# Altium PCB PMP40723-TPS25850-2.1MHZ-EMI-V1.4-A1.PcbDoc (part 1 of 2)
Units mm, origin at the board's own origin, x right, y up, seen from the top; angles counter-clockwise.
Board outline 50 x 35 mm, 4 copper layers (Top Layer, Signal Layer 1, Signal Layer 2, Bottom Layer), stack 1.647 mm thick; 79 components, 26 nets, 228 pads, 232 vias.
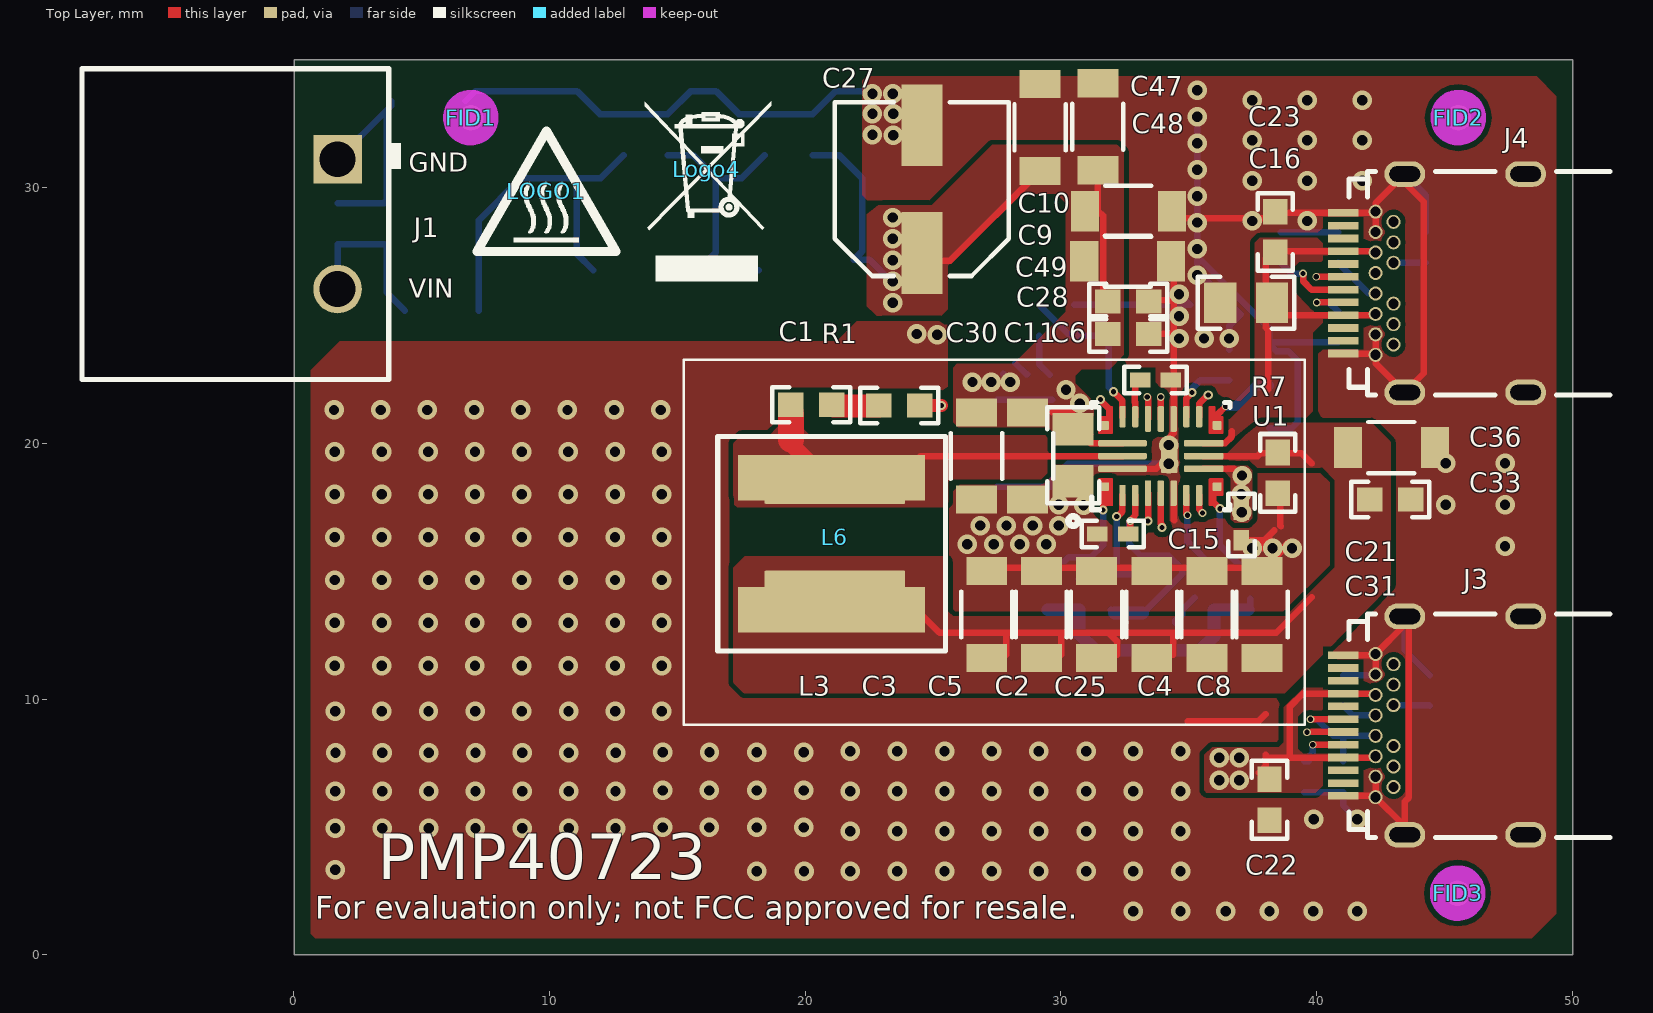
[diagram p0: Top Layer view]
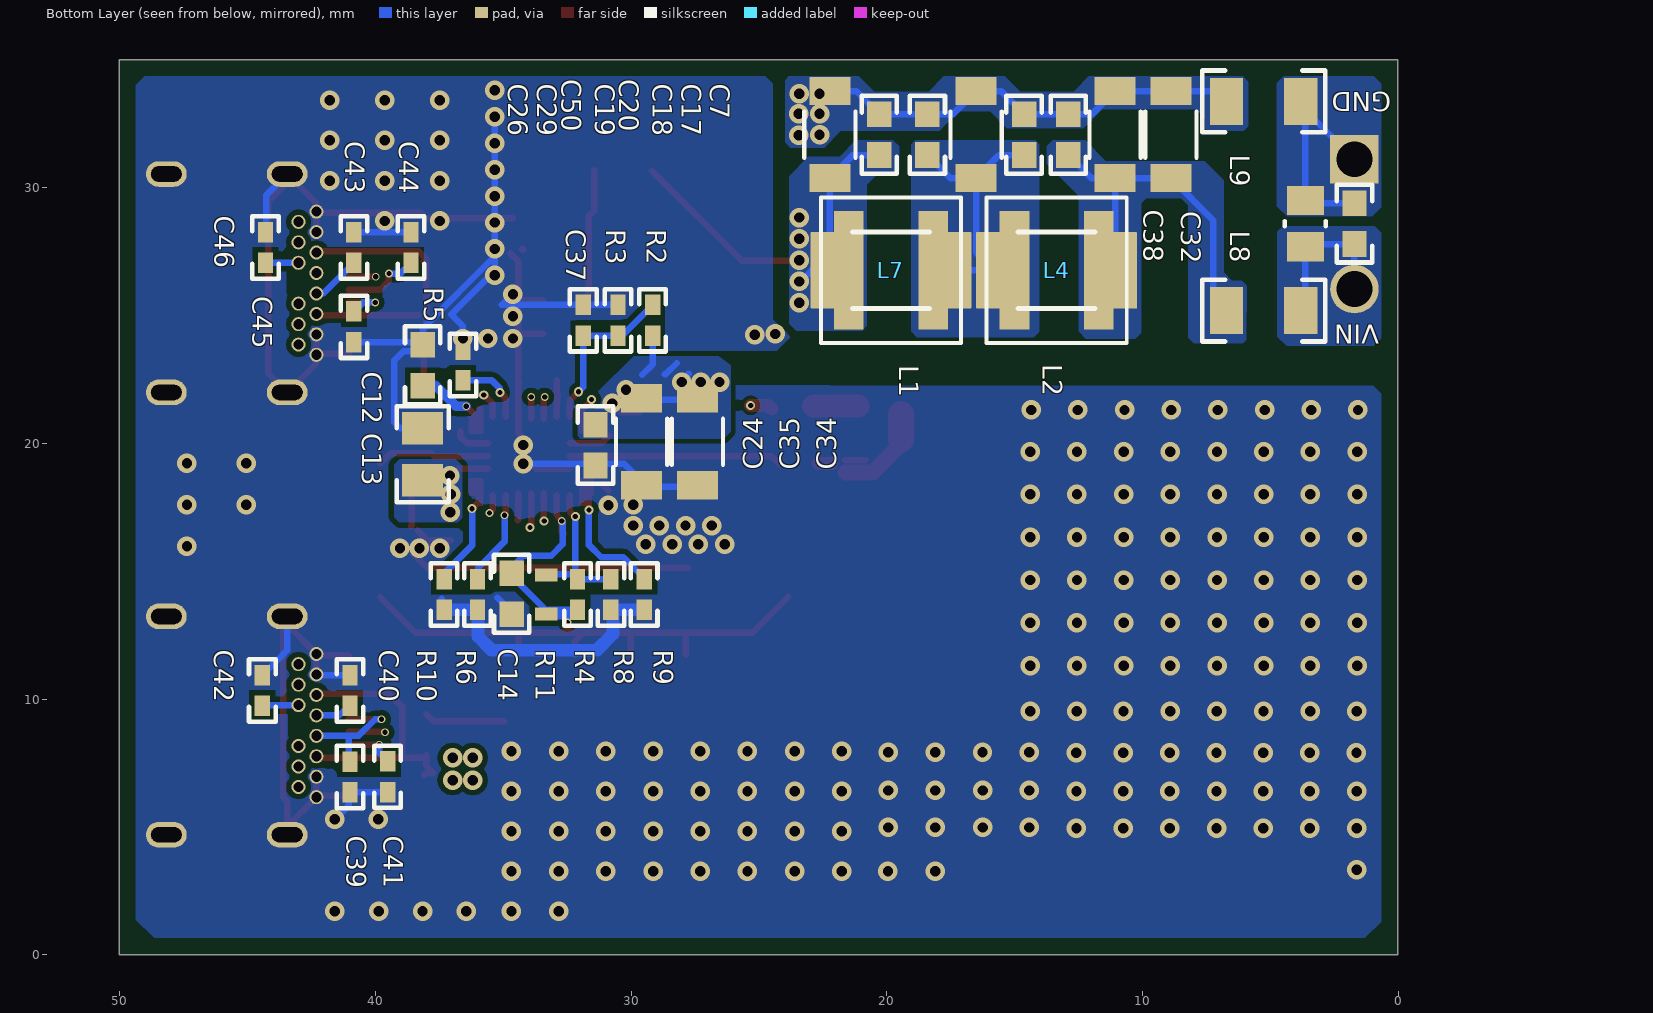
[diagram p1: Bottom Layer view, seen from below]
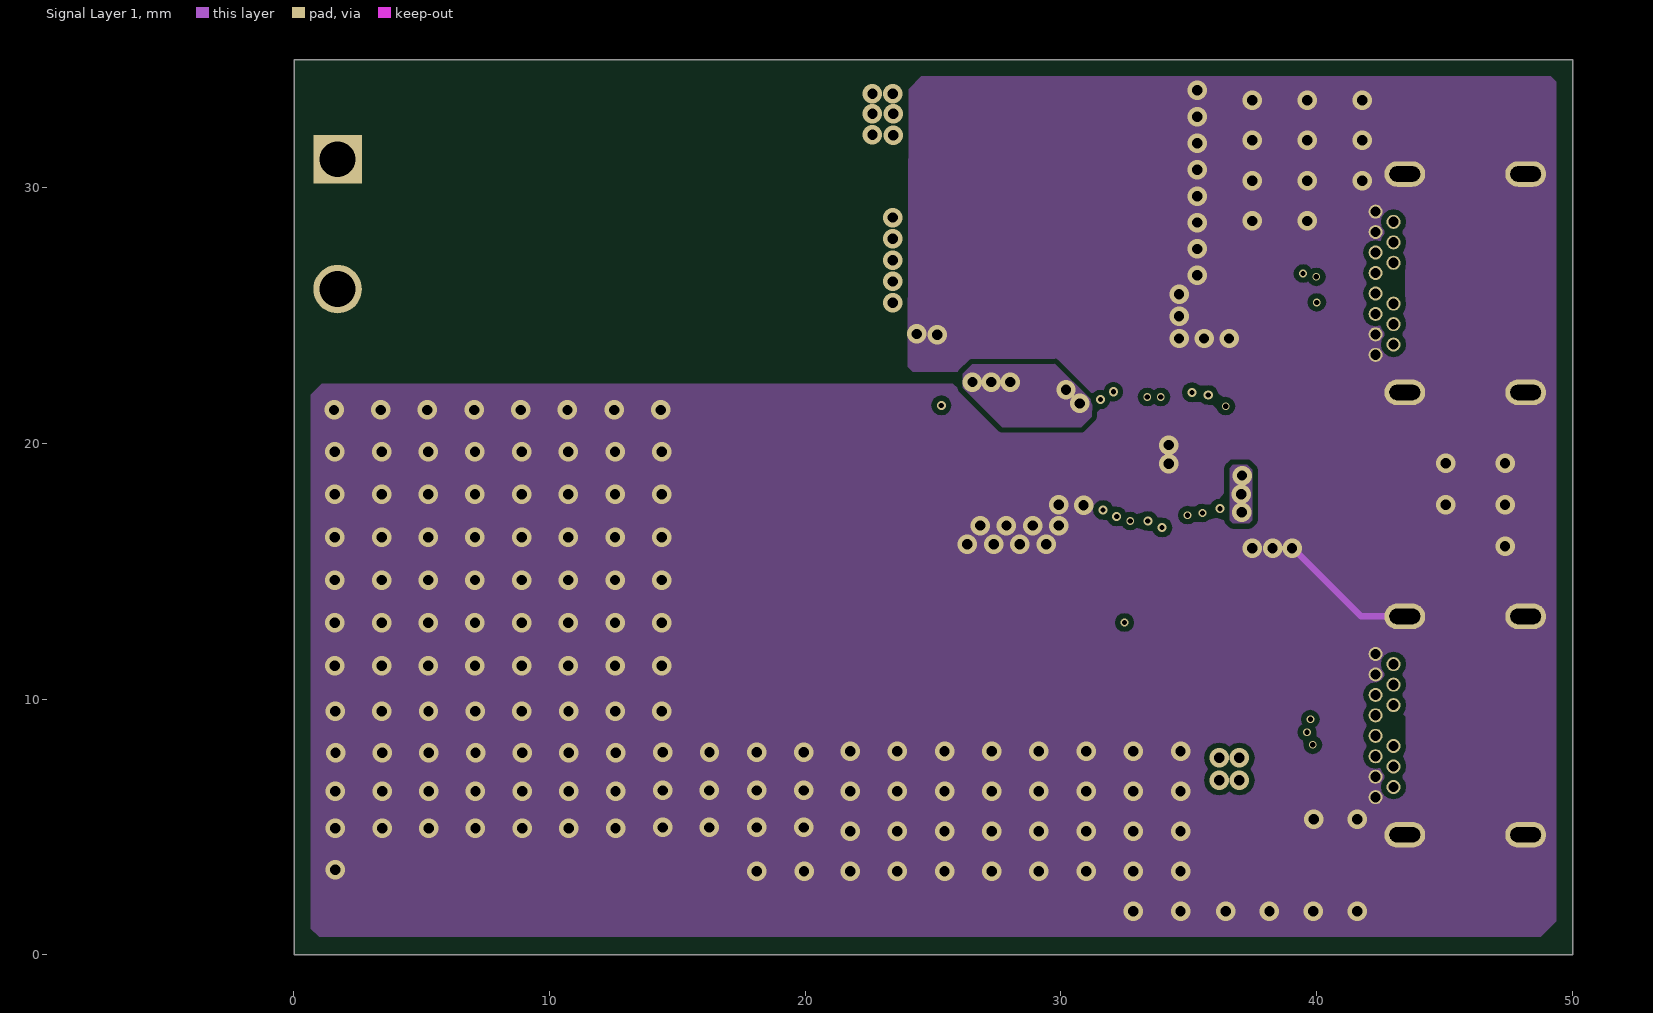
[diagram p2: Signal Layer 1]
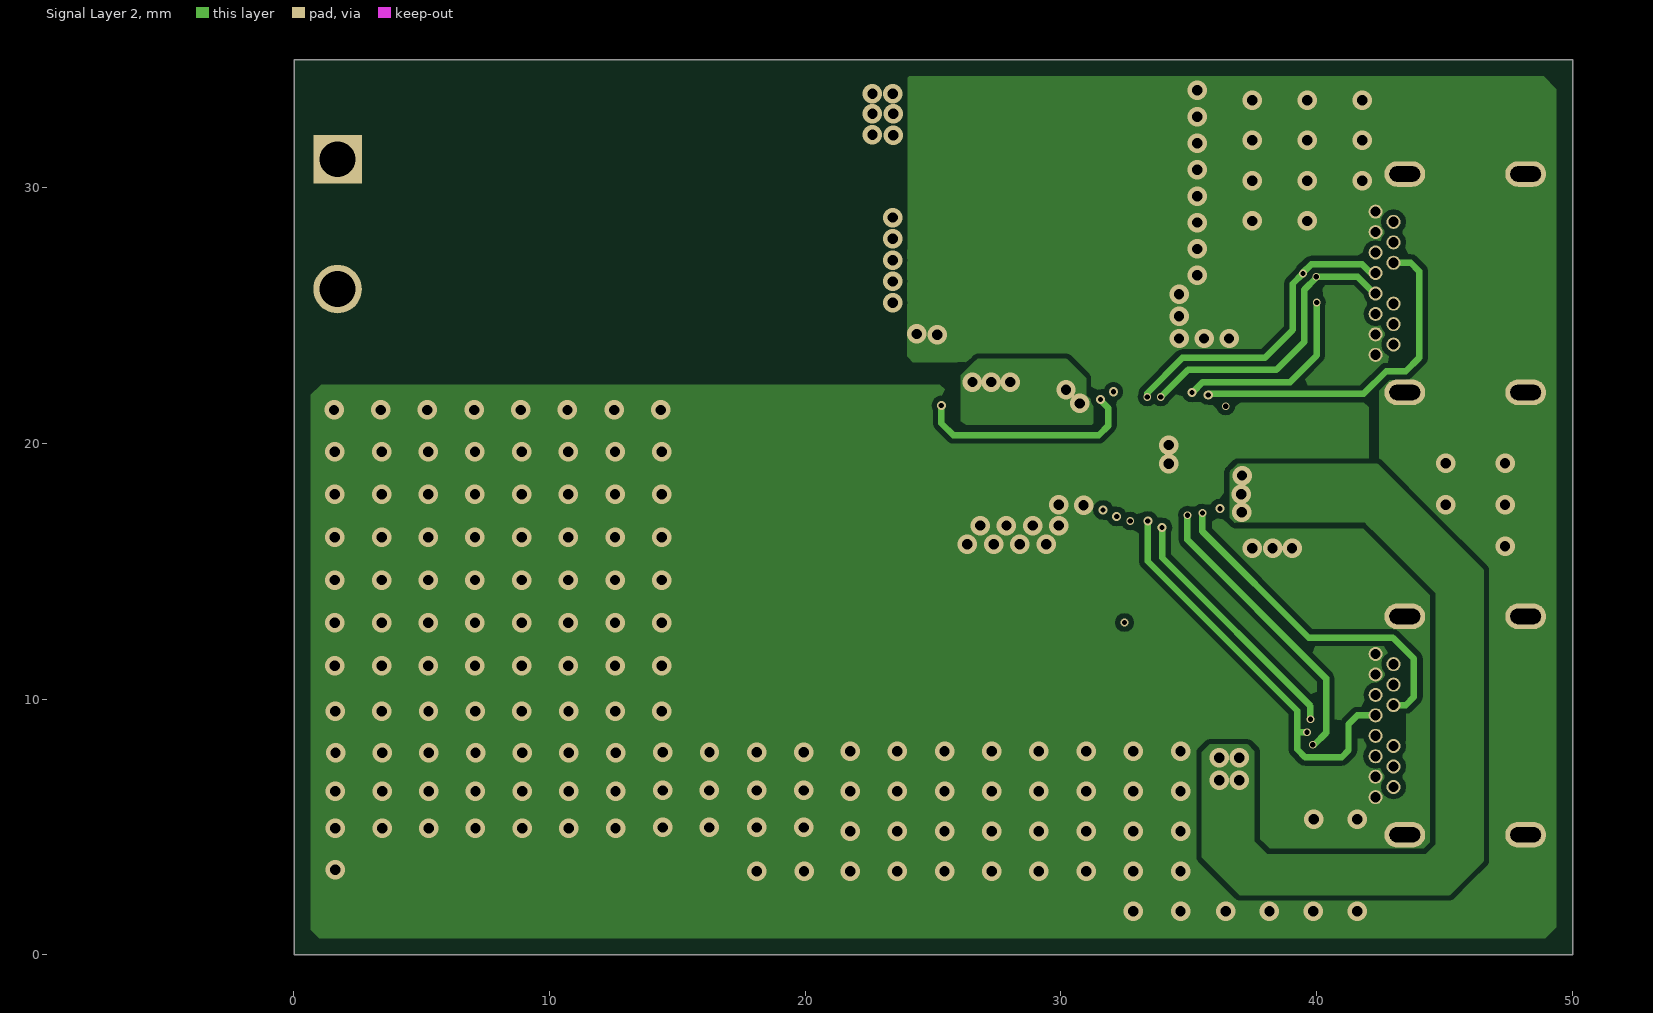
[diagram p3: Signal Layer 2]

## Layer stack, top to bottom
Top Solder: solder mask 0.0102, Solder Resist, Dk 3.5
Top Layer: signal copper 0.0356
Signal Layer 1: signal copper 0.036
Signal Layer 2: signal copper 0.036
Dielectric1: core 1.5037, FR-4, Dk 4.8
Bottom Layer: signal copper 0.0356
Bottom Solder: solder mask 0.0102, Solder Resist, Dk 3.5

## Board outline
0.021,0 0.021,35 50.021,35 50.021,0

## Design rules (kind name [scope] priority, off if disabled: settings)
AcuteAngle [All] p1: minimum=4.50000000000000E+0001 checktracksonly=FALSE
AssemblyTestPointUsage [All] p1: valid=2
BoardOutlineClearance BoardOutlineClearance_MountingHoles [OnCopper and InComponentClass('Mounting Holes')] p1: gap=0.635 ignorepadtopadclearanceinfootprint=FALSE
BoardOutlineClearance BoardOutlineClearance_Poly [OnCopper and IsPoly] p2: gap=0.635 ignorepadtopadclearanceinfootprint=FALSE
BoardOutlineClearance [OnCopper and Not InComponentClass('Logo') and not InComponentClass('FiducialMark') and not InRegion(1000,500,4000,800) and not InPoly] p3: gap=0.61 ignorepadtopadclearanceinfootprint=FALSE
Clearance Clearance_1 [All] p1: gap=0.203 ignorepadtopadclearanceinfootprint=FALSE
Clearance Clearance_Keepouts [((IsTrack Or IsArc) And Not InPoly) And IsFree and IsKeepOut vs ((IsTrack Or IsArc) And Not InPoly) And IsFree and IsKeepOut] p2: gap=0 ignorepadtopadclearanceinfootprint=FALSE
Clearance Clearance_Poly [InPolygon] p3: gap=0.254 ignorepadtopadclearanceinfootprint=TRUE
Clearance Clearance_FiducialMark [IsKeepOut and InComponentClass('FiducialMark') vs IsPad and InComponentClass('FiducialMark')] p4: gap=0 ignorepadtopadclearanceinfootprint=FALSE
Clearance [All] p5: gap=0.152 ignorepadtopadclearanceinfootprint=TRUE
ComponentClearance ComponentClearance_MountingHoles_FiducialMarks [InComponentClass('Mounting Holes') vs InComponentClass('FiducialMark')] p1: gap=1.27 collisioncheckmode=3 verticalgap=0.254 showdistances=FALSE
ComponentClearance ComponentClearance_Shunt [InComponentClass('Header') vs InComponentClass('Shunt')] p2: gap=0 collisioncheckmode=3 verticalgap=0 showdistances=FALSE
ComponentClearance ComponentClearance_Logo [InComponentClass('Logo')] p3: gap=1.27 collisioncheckmode=3 verticalgap=0.254 showdistances=FALSE
ComponentClearance ComponentClearance_ScrewToNut [(HasFootprint('NY PMS 440 0025 PH')) vs (HasFootprint('Keystone_1902C'))] p4: gap=0.127 collisioncheckmode=3 verticalgap=0.254 showdistances=FALSE
ComponentClearance ComponentClearance_MountingHoles [InComponentClass('Mounting Holes')] p5: gap=6.35 collisioncheckmode=3 verticalgap=2540 showdistances=FALSE
ComponentClearance ComponentClearance_SmallPassives [HasFootprint('0201*') or HasFootprint('0402*') or HasFootprint('0508') or HasFootprint('0603*') or HasFootprint('0612') or HasFootprint('0805*') or HasFootprint('0815*') or HasFootprint('0830*') or HasFootprint('1206*') or HasFootprint('1210*') or HasFootprint('1808*') or HasFootprint('1812*') or HasFootprint('1825*') or HasFootprint('2010*') or HasFootprint('2220*') or HasFootprint('2225*') or HasFootprint('2512*') or HasFootprint('2728*') or HasFootprint('3518*') vs HasFootprint('0201*') or HasFootprint('0402*') or HasFootprint('0508') or HasFootprint('0603*') or HasFootprint('0612') or HasFootprint('0805*') or HasFootprint('0815*') or HasFootprint('0830*') or HasFootprint('1206*') or HasFootprint('1210*') or HasFootprint('1808*') or HasFootprint('1812*') or HasFootprint('1825*') or HasFootprint('2010*') or HasFootprint('2220*') or HasFootprint('2225*') or HasFootprint('2512*') or HasFootprint('2728*') or HasFootprint('3518*')] p6: gap=0.254 collisioncheckmode=3 verticalgap=0.254 showdistances=FALSE
ComponentClearance ComponentClearance_THtoSMT [IsThruComponent vs IsSMTComponent] p7: gap=1.016 collisioncheckmode=3 verticalgap=0.762 showdistances=FALSE
ComponentClearance ComponentClearance_THtoTH [IsThruComponent vs IsThruComponent] p8: gap=0.762 collisioncheckmode=3 verticalgap=0.762 showdistances=FALSE
ComponentClearance [All] p9: gap=0.762 collisioncheckmode=3 verticalgap=0.254 showdistances=FALSE
DiffPairsRouting [All] p1: maxlimit=2.54 minlimit=0.203 mostfreqgap=0.254 toplayer_minwidth=0.254 toplayer_maxwidth=0.381 toplayer_prefwidth=0.254 midlayer1_minwidth=0.254 midlayer1_maxwidth=0.381 midlayer1_prefwidth=0.254 midlayer2_minwidth=0.254 midlayer2_maxwidth=0.381 midlayer2_prefwidth=0.254 bottomlayer_minwidth=0.254 bottomlayer_maxwidth=0.381 bottomlayer_prefwidth=0.254 maxuncoupledlength=25.4
FabricationTestPointUsage TestPointUsage [All] p1: valid=2 allowmultiple=FALSE
FabricationTestpoint Testpoint [All] p1: side=3 testpointundercomponent=TRUE minsize=1.016 maxsize=2.54 preferedsize=1.524 minholesize=0 maxholesize=1.016 preferedholesize=0.813 testpointgrid=0.025 allowsidetop=TRUE allowsidebottom=TRUE usegrid=TRUE gridtolerance=0
FanoutControl Fanout_LCC [IsLCC] p1: bgadir=Out bgaviamode=Centered fanoutstyle=Auto fanoutdirection=Alternating viagrid=0.025 // Fanout_LCC (Default Rule)
FanoutControl Fanout_BGA [IsBGA] p2: bgadir=Out bgaviamode=Centered fanoutstyle=Auto fanoutdirection=Alternating viagrid=0.025 // Fanout_BGA (Default Rule)
FanoutControl Fanout_Default [All] p4: bgadir=Out bgaviamode=Centered fanoutstyle=Auto fanoutdirection=Alternating viagrid=0.025 // Fanout_Default (Default Rule)
FanoutControl Fanout_Small [(CompPinCount < 5)] p5: bgadir=Out bgaviamode=Centered fanoutstyle=Auto fanoutdirection=OutThenIn viagrid=0.025 // Fanout_Small (Default Rule)
HoleSize [All] p1: absolutevalues=TRUE maxlimit=6.375 minlimit=0.2 maxpercent=80.000 minpercent=20.000
HoleToHoleClearance [All] p1: gap=0.203 allowstackedmicrovias=TRUE
MinimumAnnularRing MinimumAnnularRing_ThermalPadVias [IsVia and InAnyComponent] p1: minimumring=0.076
MinimumAnnularRing [All] p2: minimumring=0.051
MinimumSolderMaskSliver MinimumSolderMaskSliver_Logo [InComponentClass('Logo') vs InComponentClass('Logo')] p1: minsoldermaskwidth=0.01
MinimumSolderMaskSliver [All] p2: minsoldermaskwidth=0.1
PlaneClearance [All] p1: clearance=0.254
PlaneConnect [All] p1: planeconnectstyle=Relief reliefexpansion=0.254 reliefentries=4 reliefconductorwidth=0.254 reliefairgap=0.254
PolygonConnect [All] p1: connectstyle=Direct reliefconductorwidth=0.254 reliefentries=4 polygonreliefangle="90 Angle" airgapwidth=0.254
RoutingVias ThermalPadVias [IsVia and InAnyComponent] p1: holewidth=0.2 width=0.5 viastyle="Through Hole" minholewidth=0.2 minwidth=0.5 maxholewidth=0.33 maxwidth=0.6
RoutingVias [All] p2: holewidth=0.406 width=0.762 viastyle="Through Hole" minholewidth=0.203 minwidth=0.305 maxholewidth=0.508 maxwidth=0.762
SilkToBoardRegionClearance [Not ((IsComment or IsDesignator) And (Hide <> 'False')) and not InRegion(1000,500,4000,800)] p1:
SilkToSilkClearance SilkToSilkClearance_Pb-FreeLogo [(HasFootprint('Pb-Free_Overlay_Medium') OR HasFootprint('Pb-Free_Overlay_Small')) vs (HasFootprint('Pb-Free_Overlay_Medium') OR HasFootprint('Pb-Free_Overlay_Small'))] p1: silktosilkclearance=0
SilkToSilkClearance [All] p2: silktosilkclearance=0.1
SilkToSolderMaskClearance SilkToComponentPadClearance [(IsPad or IsFill or IsRegion) and InAnycomponent] p1: minsilkscreentomaskgap=0.127 clearancetoexposedcopper=TRUE
SilkToSolderMaskClearance "Silk to Solder Mask Opening" [All] p2: minsilkscreentomaskgap=0.1 clearancetoexposedcopper=FALSE
SolderMaskExpansion [All] p1: expansion=0.05
UnRoutedNet [All] p1: checkbadconnections=TRUE
Width [All] p1: maxlimit=2.54 minlimit=0.152 preferedwidth=0.254 checkconnectedcopper=TRUE
12 further rules are at their usual default settings.

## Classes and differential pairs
component class PMP40723-TPS25850-2.1MHZ-EMI-V1.3-A1: C1 C2 C3 C4 C5 C6 C7 C8 C9 C10 C11 C12 C13 C14 C15 C16 C17 C18 C19 C20 C21 C22 C23 C24 C25 C26 C27 C28 C29 C30 C31 C32 C33 C34 C35 C36 C37 C38 C39 C40 C41 C42 C43 C44 C45 C46 C47 C48 C49 C50 C? J1 J3 J4 L1 L2 L3 L4 L6 L7 L8 L9 R1 R2 R3 R4 R5 R6 R7 R8 R9 R10 R? RT1 U1
component class PMP40723-TPS25850-2.1MHZ-EMI-V1.3-A0: FID1 FID2 FID3 LOGO1 Logo2 Logo3 Logo4
component class FiducialMark: FID1 FID2 FID3

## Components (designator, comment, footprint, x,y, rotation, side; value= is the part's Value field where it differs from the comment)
C1 "C0603C104K5RACAUTO" 0603 20.239,21.514 r0 top value=0.1uF
C2 "GRM31CR71A226ME15L" 1206_180 31.39,13.31 r90 top value=22uF
C3 "GRM31CR71A226ME15L" 1206_180 27.097,13.31 r90 top value=22uF
C4 "GRM31CR71A226ME15L" 1206_180 35.708,13.31 r90 top value=22uF
C5 "GRM31CR71A226ME15L" 1206_180 29.231,13.31 r90 top value=22uF
C6 "CL21B104MBCNNNC" 0805_HV 30.475,19.533 r270 top value=0.1uF
C7 "CGA5L1X7R1H106K160AC" 1206_190 8.885,32.08 r90 bottom value=10uF
C8 "GRM31CR71A226ME15L" 1206_180 37.867,13.31 r90 top value=22uF
C9 "GRT31CR61H106KE01L" 1206_180 32.609,27.127 r0 top value=10uF
C10 "GRT31CR61H106KE01L" 1206_180 32.634,29.083 r0 top value=10uF
C11 "GRT31CR61H106KE01L" 1206_180 28.697,19.509 r270 top value=10uF
C12 "885012106018" 0603 38.146,23.063 r90 bottom value=2.2uF
C13 "C2012X7R1A106M125AC" 0805_HV 38.147,19.584 r90 bottom value=10uF
C14 "885012106018" 0603 34.666,14.123 r270 bottom value=2.2uF
C15 "GRM155R71C104JA88D" 0402 32.025,16.459 r180 top value=0.1uF
C16 "C2012X7R1A106M125AC" 0805_HV 37.236,25.502 r180 top value=10uF
C17 "GCM31CR71H225KA55L" 1206_180 11.07,32.08 r90 bottom value=2.2uF
C18 "C0603C222K5RACTU" 0603 12.898,32.08 r90 bottom value=2200pF
C19 "GCM31CR71H225KA55L" 1206_180 16.505,32.08 r90 bottom value=2.2uF
C20 "C0603C222K5RACTU" 0603 14.626,32.08 r90 bottom value=2200pF
C21 "C0603C104K5RACAUTO" 0603 38.476,18.847 r270 top value=0.1uF
C22 "C0603C104K5RACAUTO" 0603 38.154,6.071 r270 top value=0.1uF
C23 "C0603C104K5RACAUTO" 0603 38.379,28.27 r90 top value=0.1uF
C24 "C0603C104K5RACAUTO" 0603 31.39,19.939 r270 bottom value=0.1uF
C25 "GRM31CR71A226ME15L" 1206_180 33.549,13.31 r90 top value=22uF
C26 "CGA5L3X7R1H475K160AE" 1206_190 22.22,32.08 r90 bottom value=4.7uF
C27 "EEE-FK1V101XP" SM_RADIAL_D8 24.557,29.947 r90 top value=100uF
C28 "GCM188R71H472KA37D" 0603 32.634,24.283 r0 top value=4700pF
C29 "GRM188R71H332KA01D" 0603 20.29,32.08 r90 bottom value=3300pF
C30 "GRT31CR61H106KE01L" 1206_180 26.691,19.507 r270 top value=10uF
C31 "GRM155R71C104JA88D" 0402 37.054,16.815 r270 top value=0.1uF
C32 "C0603C104K5RACAUTO" 0603 1.706,28.601 r90 bottom value=0.1uF
C33 "C0603X222K5RACTU" 0603 42.87,17.806 r0 top value=2200pF
C34 "GRT31CR61H106KE01L" 1206_180 27.402,20.066 r270 bottom value=10uF
C35 "GRT31CR61H106KE01L" 1206_180 29.586,20.066 r270 bottom value=10uF
C36 "GRM31CR71A226ME15L" 1206_180 42.921,19.838 r0 top value=22uF
C37 "C0402C104K4RACAUTO" 0402 31.866,24.816 r90 bottom value=0.1uF
C38 "CEU4J2X7R1H104K125AE" 0805_150 3.627,28.601 r90 bottom value=0.1uF
C39 "GRM155R71C104JA88D" 0402 40.991,6.96 r270 bottom value=0.1uF
C40 "GRM155R71C104JA88D" 0402 40.991,10.338 r90 bottom value=0.1uF
C41 "GRM155R71C104JA88D" 0402 39.518,6.967 r270 bottom value=0.1uF
C42 "GRM155R71C104JA88D" 0402 44.42,10.338 r90 bottom value=0.1uF
C43 "GRM155R71C104JA88D" 0402 40.838,27.661 r90 bottom value=0.1uF
C44 "GRM155R71C104JA88D" 0402 38.603,27.661 r90 bottom value=0.1uF
C45 "GRM155R71C104JA88D" 0402 40.838,24.562 r270 bottom value=0.1uF
C46 "GRM155R71C104JA88D" 0402 44.293,27.661 r90 bottom value=0.1uF
C47 "GRT31CR61H106KE01L" 1206_180 29.18,32.36 r90 top value=10uF
C48 "GRT31CR61H106KE01L" 1206_180 31.44,32.385 r90 top value=10uF
C49 "C0603C104K5RACAUTO" 0603 32.634,25.553 r0 top value=0.1uF
C50 "C0603C222K5RACTU" 0603 18.41,32.08 r90 bottom value=2200pF
FID1 "Fiducial" Fiducial10-20 6.92,32.741 r0 top
FID2 "Fiducial" Fiducial10-20 45.537,32.741 r0 top
FID3 "Fiducial" Fiducial10-20 45.512,2.413 r0 top
J1 "1757242" PHOENIX_1757242 -2.291,28.575 r270 top locked
J3 "632723300011" Wurth_632_723_300_011 51.624,8.967 r90 top locked (schematic designator J1)
J4 "632723300011" Wurth_632_723_300_011 51.624,26.267 r90 top locked
L1 "74279252" 1812_170_HighSpeed 19.833,26.772 r0 bottom value="880 ohm"
L2 "XAL5030-102MEB" XAL5030 13.356,26.772 r0 bottom value=1uH
L3 "XAL8080-102ME" XAL8080 21.026,16.078 r270 top value=4.7uH
L4 "NC" 1812_170_HighSpeed 13.356,26.772 r0 bottom value="880 ohm"
L6 "XAL6060-472MEB" XAL6060 21.153,16.332 r270 top value=4.7uH
L7 "XAL5030-102MEB" XAL5030 19.833,26.772 r0 bottom value=1uH
L8 "MPZ2012S300ATD25" 1206 5.256,25.197 r0 bottom value="110 ohm"
L9 "MPZ2012S300ATD25" 1206 5.256,33.376 r0 bottom value="110 ohm"
LOGO1 "CAUTION HOT SURFACE" IEC_HotSurface_Small 9.876,29.871 r0 top
Logo3 "FCC disclaimer" FCC_disclaimer -11.366,-5.562 r0 top
Logo4 "WEEE logo" WEEE_Minimum 16.15,30.723 r0 top
R1 "RMCF0603ZT0R00" 0603 23.668,21.489 r180 top value=0
R2 "CRCW040220K0JNED" 0402 29.154,24.816 r270 bottom value=20k
R3 "CRCW04025K10JNED" 0402 30.51,24.816 r270 bottom value=5.1k
R4 "ERJ-2GEJ393X" 0402 32.092,14.097 r270 bottom value=39k
R5 "CRCW04025K10JNED" 0402 36.571,23.063 r270 bottom value=5.1k
R6 "CRCW04025K10JNED" 0402 36.004,14.097 r90 bottom value=5.1k
R7 "CRCW04028K87FKED" 0402 33.701,22.479 r180 top value=8.87k
R8 "ERJ-2GEJ393X" 0402 30.788,14.097 r90 bottom value=39k
R9 "MCR01MZPJ000" 0402 29.485,14.097 r90 bottom value=0
R10 "MCR01MZPJ000" 0402 37.308,14.097 r90 bottom value=0
RT1 "NCP18WM474J03RB" 0603S 33.312,14.097 r270 bottom value=470k
U1 "TPS25850QRPQRQ1" RPQ0025A 33.904,19.507 r90 top locked

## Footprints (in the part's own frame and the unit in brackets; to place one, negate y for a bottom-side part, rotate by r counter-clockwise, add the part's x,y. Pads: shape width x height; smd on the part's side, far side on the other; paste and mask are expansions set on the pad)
0402 [mm] "0402 from SM-752 data"
  rect 0.8x0.6 smd: 1(-0.6,0) 2(0.6,0)
  silkscreen extent -1.22,-0.52 1.22,0.52, body extent -0.55,-0.3 0.55,0.3, height 0.6
0603 [mm] "0603 from SM-752 data"
  rect 1x0.95 smd: 1(-0.8,0) 2(0.8,0)
  silkscreen extent -1.52,-0.69 1.52,0.69, body extent -0.87,-0.47 0.87,0.47, height 1
0603S [mil]
  rect 20x35 smd: 1(-30,0) 2(30,0)
  body extent -34,-19 34,19, height 39
0805_150 [mm] "0805 / 1.5 mm height"
  rect 1.15x1.45 smd: 1(-0.9,0) 2(0.9,0)
  silkscreen extent -0.1,-0.8 0.1,0.8, body extent -1.1,-0.72 1.1,0.72, height 1.5
0805_HV [mil] "0805 with 30mil clearance between pads"
  rect 50x63 smd: 1(-40,0) 2(40,0)
  silkscreen extent -74,-40 74,40, body extent -43,-29 43,29, height 57
1206 [mm] "1206 from SM-752 data"
  rect 1.3x1.85 smd: 1(-1.45,0) 2(1.45,0)
  silkscreen extent -2.4,-1.21 2.4,1.21, body extent -1.7,-0.9 1.7,0.9, height 1.35
1206_180 [mm] "1206_180"
  rect 1.1x1.6 smd: 1(-1.7,0) 2(1.7,0)
  silkscreen extent -0.9,-1 0.9,1, body extent -1.75,-0.95 1.75,0.95, height 1.8
1206_190 [mm] "1206_190"
  rect 1.1x1.6 smd: 1(-1.7,0) 2(1.7,0)
  silkscreen extent -0.9,-1 0.9,1, body extent -1.75,-0.95 1.75,0.95, height 1.9
1812_170_HighSpeed [mm] "Wurth recommended land pattern"
  rrect7% 1.4x3 smd: 1(-2.45,0) 2(2.45,0)
  silkscreen extent -1.5,-1.5 1.5,1.5, body extent -2.25,-1.6 2.25,1.6, height 1.51
FCC_disclaimer [mm]
Fiducial10-20 [mm]
  round 1 smd mask+0.5: 1(0,0)
  Top Layer keep-out circle w1.178: c0,0 r0.5
IEC_HotSurface_Small [mm]
  silkscreen extent -2.72,-2.36 2.72,2.35
PHOENIX_1757242 [mm] "Header, 5.08 mm, 2x1, R/A, TH"
  rect 1.9x1.9 hole 1.4: 1(-2.54,4)
  round 1.9 hole 1.4: 2(2.54,4)
  silkscreen extent -6.08,-6 6.08,6.47, body extent -6.06,-6.02 6.1,5.98, height 8.6
RPQ0025A [mm] "VQFN-25"
  rrect29% 0.35x0.35 smd: 1(-1.2,2.2) 9(-1.2,-2.2) 13(1.2,-2.2) 21(1.2,2.2)
  rrect40% 0.825x0.25 smd: 2(-1.538,1.5) 3(-1.538,1) 7(-1.538,-1) 8(-1.538,-1.5) 14(1.538,-1.5) 15(1.538,-1) 19(1.538,1) 20(1.538,1.5)
  rrect40% 1x0.25 smd: 4(-1.45,0.5) 5(-1.45,0) 6(-1.45,-0.5) 16(1.45,-0.5) 17(1.45,0) 18(1.45,0.5)
  rrect40% 0.25x1.55 smd paste-1.55: 10(-0.5,-1.675) 11(0,-1.675) 12(0.5,-1.675)
  rrect40% 0.25x1.9 smd paste-1.55: 22(0.5,1.5) 23(0,1.5) 24(-0.5,1.5)
  rrect15% 1.325x0.65 smd paste-1.325: 25(0,-0.325)
  Top Layer region: -1.95,1.925 -1.95,2.075 -1.946,2.094 -1.935,2.11 -1.919,2.121 -1.9,2.125 -1.9,2.125 -1.6,2.125 -1.581,2.129 -1.565,2.14 -1.554,2.156 -1.55,2.175 -1.55,2.175 -1.55,2.4 -1.546,2.419 -1.535,2.435 -1.519,2.446 -1.5,2.45 -1.5,2.45 -0.925,2.45 -0.906,2.446 -0.89,2.435 -0.879,2.419 -0.875,2.4 -0.875,2.4 -0.875,1.925 -0.879,1.906 -0.89,1.89 -0.906,1.879 -0.925,1.875 -0.925,1.875 -1.9,1.875 -1.919,1.879 -1.935,1.89 -1.946,1.906 -1.95,1.925
  Top Layer region: -1.95,-1.925 -1.95,-2.075 -1.946,-2.094 -1.935,-2.11 -1.919,-2.121 -1.9,-2.125 -1.9,-2.125 -1.6,-2.125 -1.581,-2.129 -1.565,-2.14 -1.554,-2.156 -1.55,-2.175 -1.55,-2.175 -1.55,-2.4 -1.546,-2.419 -1.535,-2.435 -1.519,-2.446 -1.5,-2.45 -1.5,-2.45 -0.925,-2.45 -0.906,-2.446 -0.89,-2.435 -0.879,-2.419 -0.875,-2.4 -0.875,-2.4 -0.875,-1.925 -0.879,-1.906 -0.89,-1.89 -0.906,-1.879 -0.925,-1.875 -0.925,-1.875 -1.9,-1.875 -1.919,-1.879 -1.935,-1.89 -1.946,-1.906 -1.95,-1.925
  Top Layer region: 1.95,-1.925 1.95,-2.075 1.946,-2.094 1.935,-2.11 1.919,-2.121 1.9,-2.125 1.9,-2.125 1.6,-2.125 1.575,-2.132 1.557,-2.15 1.55,-2.175 1.55,-2.175 1.55,-2.4 1.546,-2.419 1.535,-2.435 1.519,-2.446 1.5,-2.45 1.5,-2.45 0.925,-2.45 0.906,-2.446 0.89,-2.435 0.879,-2.419 0.875,-2.4 0.875,-2.4 0.875,-1.925 0.882,-1.9 0.9,-1.882 0.925,-1.875 0.925,-1.875 1.9,-1.875 1.919,-1.879 1.935,-1.89 1.946,-1.906 1.95,-1.925
  Top Layer region: 1.95,1.925 1.95,2.075 1.946,2.094 1.935,2.11 1.919,2.121 1.9,2.125 1.9,2.125 1.6,2.125 1.575,2.132 1.557,2.15 1.55,2.175 1.55,2.175 1.55,2.4 1.546,2.419 1.535,2.435 1.519,2.446 1.5,2.45 1.5,2.45 0.925,2.45 0.906,2.446 0.89,2.435 0.879,2.419 0.875,2.4 0.875,2.4 0.875,1.925 0.882,1.9 0.9,1.882 0.925,1.875 0.925,1.875 1.9,1.875 1.919,1.879 1.935,1.89 1.946,1.906 1.95,1.925
  silkscreen extent -2.1,-2.7 2.1,2.7, body extent -1.75,-2.25 1.75,2.25, height 1
SM_RADIAL_D8 [mm] "6.3 x 7.7mm:  Panasonic D8"
  rect 3.2x1.6 smd: 1(-2.5,0) 2(2.5,0)
  silkscreen extent -3.4,-3.4 3.4,3.4, body extent -3.4,-3.4 3.4,3.4, height 8.01
WEEE_Minimum [mm] "WEEElie bin"
  silkscreen extent -2.42,-4.38 2.52,2.65
Wurth_632_723_300_011 [mm] "Connector, Receptacle, USB Type C, R/A"
  rect 0.3x1.2 smd: A1(-2.75,10.58) A2(-2.25,10.58) A3(-1.75,10.58) A4(-1.25,10.58) A5(-0.75,10.58) A6(-0.25,10.58) A7(0.25,10.58) A8(0.75,10.58) A9(1.25,10.58) A10(1.75,10.58) A11(2.25,10.58) A12(2.75,10.58)
  round 0.55 hole 0.4: B1(2.8,9.32) B2(2.4,8.62) B3(1.6,8.62) B4(1.2,9.32) B5(0.8,8.62) B6(0.4,9.32) B7(-0.4,9.32) B8(-0.8,8.62) B9(-1.2,9.32) B10(-1.6,8.62) B11(-2.4,8.62) B12(-2.8,9.32) M1(2,9.32) M2(-2,9.32)
  rrect100% 1x1.6 hole 0.6 slot 1.2 at 90 deg: S1(-4.27,8.18) S2(-4.27,3.45) S3(4.27,3.45) S4(4.27,8.18)
  silkscreen extent -4.37,0.15 4.37,10.36, body extent -4.37,-0.96 4.37,10.83, height 3.07
XAL5030 [mil] "Coilcraft XAL5030 12/12/11"
  rect 46x183 smd: 1(-65,0) 2(65,0)
  silkscreen extent -108,-112 108,112, body extent -108,-112 108,112, height 122
XAL6060 [mm] "Coilcraft recommended land pattern Document 887-4 Revised 01/14/18"
  rrect7% 1.43x5.5 smd: 1(-2.019,0) 2(2.019,0)
  body extent -3.28,-3.38 3.28,3.38, height 6.11
XAL8080 [mm] "Coilcraft"
  rect 1.78x7.31 smd: 1(-2.58,0) 2(2.58,0)
  silkscreen extent -4.2,-4.45 4.2,4.45, body extent -4.15,-4.4 4.15,4.4, height 8

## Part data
C1 C21 C22 C23 C24 C49: library part CMP-0079602-1, "CAP, CERM, 0.1 µF, 50 V,+/- 10%, X7R, AEC-Q200 Grade 1, 0603", Cap_Case=0603, Manufacturer=Kemet, Supplier Part Number 1=399-6856-1-ND, TempCo=X7R, Tolerance_%=10%, Value2=50V, ValueDisplayed=0.1µF
C2 C3 C4 C5 C8 C25 C36: library part CMP-0008960-2, "CAP, CERM, 22 uF, 10 V, +/- 20%, X7R, 1206", Cap_Case=1206, Manufacturer=MuRata, Supplier Part Number 1=490-6516-1-ND, TempCo=X7R, Tolerance_%=20%, Value1=Unknown, Value2=10V, ValueDisplayed=22uF
C6: library part CMP-0082524-1, "CAP, CERM, 0.1 µF, 50 V,+/- 20%, X7R, 0805", Cap_Case=0805, Manufacturer=Samsung, Supplier Part Number 1=1276-2450-1-ND, TempCo=X7R, Tolerance_%=20%, Value2=50V, ValueDisplayed=0.1µF
C7: library part CMP-0085950-1, "CAP, CERM, 10 µF, 50 V,+/- 10%, X7R, AEC-Q200 Grade 1, 1206", Cap_Case=1206, Manufacturer=TDK, TempCo=X7R, Tolerance_%=10%, Value2=50V, ValueDisplayed=10µF
C9 C10 C11 C34 C35 C47 C48: library part CMP-0009015-1, "CAP, CERM, 10 uF, 50 V, +/- 10%, X5R, AEC-Q200 Grade 1, 1206", Cap_Case=1206, Manufacturer=MuRata, Supplier Part Number 1=490-12456-1-ND, TempCo=X5R, Tolerance_%=10%, Value1=Unknown, Value2=50V, ValueDisplayed=10uF
C12 C14: library part CMP-0006825-5, "CAP, CERM, 2.2 uF, 16 V, +/- 20%, X5R, 0603", Cap_Case=0603, Manufacturer="Wurth Elektronik", Supplier Part Number 1=732-7915-1-ND, TempCo=X5R, Tolerance_%=20%, Value1=Unknown, Value2=16V, ValueDisplayed=2.2uF
C13 C16: library part CMP-0007864-2, "CAP, CERM, 10 uF, 10 V, +/- 20%, X7R, 0805", Cap_Case=0805, Manufacturer=TDK, Supplier Part Number 1=445-7592-1-ND, TempCo=X7R, Tolerance_%=20%, Value1=Unknown, Value2=10V, ValueDisplayed=10uF
C15 C31 C39 C40 C41 C42 C43 C44 C45 C46: library part CMP-0006640-2, "CAP, CERM, 0.1 uF, 16 V, +/- 5%, X7R, 0402", Cap_Case=0402, Manufacturer=MuRata, Supplier Part Number 1=490-6327-1-ND, TempCo=X7R, Tolerance_%=5%, Value1=Unknown, Value2=16V, ValueDisplayed=0.1uF
C17 C19: library part CMP-0008814-2, "CAP, CERM, 2.2 uF, 50 V, +/- 10%, X7R, AEC-Q200 Grade 1, 1206", Cap_Case=1206, Manufacturer=MuRata, Supplier Part Number 1=490-4796-1-ND, TempCo=X7R, Tolerance_%=10%, Value1=Unknown, Value2=50V, ValueDisplayed=2.2uF
C18 C20 C50: library part CMP-0006898-4, "CAP, CERM, 2200 pF, 50 V, +/- 10%, X7R, 0603", Cap_Case=0603, Manufacturer=Kemet, Supplier Part Number 1=399-1085-1-ND, TempCo=X7R, Tolerance_%=10%, Value1=Unknown, Value2=50V, ValueDisplayed=2200pF
C26: library part CMP-0085349-1, "CAP, CERM, 4.7 µF, 50 V,+/- 10%, X7R, AEC-Q200 Grade 1, 1206", Cap_Case=1206, Manufacturer=TDK, TempCo=X7R, Tolerance_%=10%, Value2=50V, ValueDisplayed=NC
C27: library part CMP-0010724-1, "CAP, AL, 100 uF, 35 V, +/- 20%, 0.34 ohm, AEC-Q200 Grade 2, SMD", Cap_Case=D8, Manufacturer=Panasonic, Supplier Part Number 1=PCE3836CT-ND, Tolerance_%=20%, Value1="0.34 ohm", Value2=35V, ValueDisplayed=100uF
C28: library part CMP-0007146-4, "CAP, CERM, 4700 pF, 50 V, +/- 10%, X7R, AEC-Q200 Grade 1, 0603", Cap_Case=0603, Manufacturer=MuRata, Supplier Part Number 1=490-4932-1-ND, TempCo=X7R, Tolerance_%=10%, Value1=Unknown, Value2=50V, ValueDisplayed=4700pF
C29: library part CMP-0007450-4, "CAP, CERM, 3300 pF, 50 V, +/- 10%, X7R, 0603", Cap_Case=0603, Manufacturer=MuRata, Supplier Part Number 1=490-1503-1-ND, TempCo=X7R, Tolerance_%=10%, Value1=Unknown, Value2=50V, ValueDisplayed=3300pF
C30: library part CMP-0009015-1, "CAP, CERM, 10 uF, 50 V, +/- 10%, X5R, AEC-Q200 Grade 1, 1206", Cap_Case=1206, Manufacturer=MuRata, Supplier Part Number 1=490-12456-1-ND, TempCo=X5R, Tolerance_%=10%, Value1=Unknown, Value2=50V, ValueDisplayed=NC
C32: library part CMP-0079602-1, "CAP, CERM, 0.1 µF, 50 V,+/- 10%, X7R, AEC-Q200 Grade 1, 0603", Cap_Case=0603, Manufacturer=Kemet, Supplier Part Number 1=399-6856-1-ND, TempCo=X7R, Tolerance_%=10%, Value2=50V, ValueDisplayed=NC
C33: library part CMP-0006983-4, "CAP, CERM, 2200 pF, 50 V, +/- 10%, X7R, 0603", Cap_Case=0603, Manufacturer=Kemet, Supplier Part Number 1=399-5341-1-ND, TempCo=X7R, Tolerance_%=10%, Value1=Unknown, Value2=50V, ValueDisplayed=2200pF
C37: library part CMP-0006237-2, "CAP, CERM, 0.1 uF, 16 V, +/- 10%, X7R, AEC-Q200 Grade 1, 0402", Cap_Case=0402, Manufacturer=Kemet, Supplier Part Number 1=399-6828-1-ND, TempCo=X7R, Tolerance_%=10%, Value1=Unknown, Value2=16V, ValueDisplayed=0.1uF
C38: library part CMP-0007961-2, "CAP, CERM, 0.1 uF, 50 V, +/- 10%, X7R, AEC-Q200 Grade 1, 0805", Cap_Case=0805, Manufacturer=TDK, Supplier Part Number 1=445-7856-1-ND, TempCo=X7R, Tolerance_%=10%, Value1=Unknown, Value2=50V, ValueDisplayed=0.1uF
FID1 FID2 FID3: library part CMP-0077181-1, "Fiducial mark.  There is nothing to buy or mount.", Manufacturer=N/A
J1: library part CMP-0055534-1, "Header (Shrouded), 5.08 mm, 2x1, Tin, R/A, TH", Manufacturer="Phoenix Contact", Supplier Part Number 1=277-1106-ND
J3 J4: library part CMP-0080891-1, "Connector, Receptacle, USB Type C, R/A", Color=Black, Current_A=3A, Manufacturer="Wurth Elektronik", Supplier Part Number 1=732-9618-1-ND, Voltage_V=5V
L1: library part CMP-0003170-1, "Ferrite Bead, 880 ohm @ 100 MHz, 4 A, 1812", Manufacturer="Wurth Elektronik", Value1="0.035 ohm", Value2=4A, ValueDisplayed="880 ohm"
L2: library part CMP-0082088-1, "Inductor, Shielded, CAPPR7.5-16X20, 1 µH, 11.1 A, 0.0094 ohm, AEC-Q200 Grade 1, SMD", Manufacturer=Coilcraft, Value1="0.0094 ohm", Value2=11.1A, ValueDisplayed=1µH
L3: library part CMP-0061062-1, "Inductor, Shielded, Composite, 4.7 uH, 10.5 A, 0.00889 ohm, SMD", Manufacturer=Coilcraft, PartNumber=XAL8080-472ME, Supplier Part Number 1=994-XAL8080-472MEB, Value1="0.00889 ohm", Value2=10.5A, ValueDisplayed=NC
L4: library part CMP-0003170-1, "Ferrite Bead, 880 ohm @ 100 MHz, 4 A, 1812", Manufacturer="Wurth Elektronik", PartNumber=74279252, Value1="0.035 ohm", Value2=4A, ValueDisplayed="880 ohm"
L6: library part CMP-0061020-2, "Inductor, Shielded, Composite, 4.7 µH, 10.5 A, 0.0144 ohm, AEC-Q200 Grade 1, SMD", Manufacturer=Coilcraft, Value1="0.0144 ohm", Value2=10.5A, ValueDisplayed=1uH
L7: library part CMP-0082088-1, "Inductor, Shielded, CAPPR7.5-16X20, 1 µH, 11.1 A, 0.0094 ohm, AEC-Q200 Grade 1, SMD", Manufacturer=Coilcraft, PartNumber=NC, Value1="0.0094 ohm", Value2=11.1A
L8 L9: library part CMP-0003139-1, "Ferrite Bead, 110 ohm @ 100 MHz, 5.4 A, 1206", Manufacturer="Wurth Elektronik", PartNumber=74279221111, Supplier Part Number 1=732-6130-1-ND, Value1="0.0095 ohm", Value2=5.4A, ValueDisplayed="110 ohm"
LOGO1: library part CMP-0074837-1, "IEC 61010-1 Hot Surface Warning"
Logo3: library part CMP-0074847-1, "FCC_disclaimer"
Logo4: library part CMP-0074769-1
R1: library part CMP-0023343-3, "RES, 0, 1%, 0.1 W, AEC-Q200 Grade 0, 0603", Manufacturer="Stackpole Electronics Inc", Power_W=100mW, Supplier Part Number 1=RMCF0603ZT0R00CT-ND, TempCo=ppm/C, Tolerance_%=1%, Value2=0.1W, Value_Code=0, ValueDisplayed=1R5
R2: library part CMP-0026875-3, "RES, 20 k, 5%, 0.063 W, AEC-Q200 Grade 0, 0402", Manufacturer=Vishay-Dale, Power_W=63mW, Supplier Part Number 1=541-20KJCT-ND, TempCo="200 ppm/C", Tolerance_%=5%, Value2=0.063W, Value_Code=20k0, ValueDisplayed=20k
R3 R5 R6: library part CMP-0026951-5, "RES, 5.1 k, 5%, 0.063 W, AEC-Q200 Grade 0, 0402", Manufacturer=Vishay-Dale, Power_W=63mW, Supplier Part Number 1=541-5.1KJCT-ND, TempCo="200 ppm/C", Tolerance_%=5%, Value2=0.063W, Value_Code=5k10, ValueDisplayed=5.1k
R4 R8: library part CMP-0026998-2, "RES, 39 k, 5%, 0.1 W, AEC-Q200 Grade 0, 0402", Manufacturer=Panasonic, Power_W=100mW, Supplier Part Number 1=P39KJCT-ND, TempCo="200 ppm/C", Tolerance_%=5%, Value2=0.1W, Value_Code=39k0, ValueDisplayed=39k
R7: library part CMP-0026592-2, "RES, 8.87 k, 1%, 0.063 W, AEC-Q200 Grade 0, 0402", Manufacturer=Vishay-Dale, Power_W=63mW, Supplier Part Number 1=541-8.87KLCT-ND, TempCo="100 ppm/C", Tolerance_%=1%, Value2=0.063W, Value_Code=8k87, ValueDisplayed=8.87k
R9 R10: library part CMP-0027002-2, "RES, 0, 5%, 0.063 W, 0402", Manufacturer=Rohm, Power_W=63mW, Supplier Part Number 1=RHM0.0JCT-ND, TempCo="500 ppm/C", Tolerance_%=5%, Value2=0.063W, Value_Code=0000, ValueDisplayed=0
RT1: library part CMP-0002545-3, "Thermistor NTC, 470k ohm, 5%, 0603", Manufacturer=MuRata, Power_W=100mW, Supplier Part Number 1=490-2433-1-ND, Tolerance_%=5%
U1: library part CMP-0860365-2, "Dual 3A USB Type-C Charging Ports Controller with Programmable Current Limit and Thermal Management, RPQ0025A (VQFN-25)", Alternate Manufacturer="Texas Instruments"

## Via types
v1: diameter 0.762, hole 0.406, Top Layer to Bottom Layer, 201 vias
v2: diameter 0.305, hole 0.203, Top Layer to Bottom Layer, 11 vias
v3: diameter 0.356, hole 0.203, Top Layer to Bottom Layer, 8 vias
v4: diameter 0.762, hole 0.406, Top Layer to Bottom Layer, tented top, 8 vias
v5: diameter 0.356, hole 0.203, Top Layer to Bottom Layer, tented top, 2 vias
v6: diameter 0.305, hole 0.203, Top Layer to Bottom Layer, tented top, 2 vias

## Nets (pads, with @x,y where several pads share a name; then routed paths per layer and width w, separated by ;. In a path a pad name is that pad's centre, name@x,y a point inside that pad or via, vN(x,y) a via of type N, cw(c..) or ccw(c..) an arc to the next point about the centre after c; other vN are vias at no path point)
+BAT: C32.1 C38.1 J1.2 L8.1 | length 6.5
  Bottom Layer w0.254: J1.2@1.709,26.035 1.709,27.798 C32.1@1.706,27.801 3.527,27.801 C38.1@3.627,27.701 3.627,25.906 L8.1@4.336,25.197
BOOT: R1.1 U1.21 | length 10.6
  Top Layer w0.254: R1.1@24.468,21.362 R1.1@24.49,21.34 ; v3(31.542,21.717) 31.542,21.692 31.593,21.641 31.898,21.336 31.898,20.901
  Top Layer w0.508: R1.1@24.49,21.34 24.639,21.489 v3(25.319,21.489)
  Signal Layer 2 w0.254: v3(25.319,21.489) 25.319,20.793 25.791,20.32 31.473,20.32 31.854,20.701 31.854,21.38 31.593,21.641 31.542,21.692 v3(31.542,21.717)
EN: C37.1 R2.1 R3.2 U1.20 | length 6.7
  Top Layer w0.254: v3(32.05,22.022) 32.404,21.668 U1.20@32.404,21.045
  Bottom Layer w0.254: R2.1@29.154,25.416 30.354,24.216 R3.2@30.51,24.216 C37.1@31.866,24.216 31.866,22.206 v3(32.05,22.022) v3@32.105,22.022 ; R3.2@30.577,24.241 R3.2@30.577,24.318
NetC1_2: C1.2 R1.2 | length 1.8
  Top Layer w0.889: C1.2@21.115,21.463 R1.2@22.868,21.463
NetC7_1: C7.1 C17.1 C18.1 L2.1 L4.1 L8.2 | length 14.1
  Bottom Layer w0.254: L8.2@7.236,25.197 7.236,28.732 C7.1@8.885,30.38 C17.1@11.07,30.38 ; L2.1@11.705,26.772 11.07,27.407 C17.1@11.07,30.38 ; C18.1@12.898,31.28 11.998,30.38 C17.1@11.07,30.38
NetC19_1: C19.1 C20.1 C50.1 L1.1 L2.2 L4.2 L7.1 | length 10.8
  Bottom Layer w0.254: C20.1@14.626,31.28 15.605,31.28 C19.1@16.505,30.38 ; L7.1@18.182,26.772 L1.1@17.383,26.772 L4.2@15.806,26.772 16.505,27.471 C19.1@16.505,30.38 ; C50.1@18.41,31.28 17.51,30.38 C19.1@16.505,30.38
NetC32_2: C32.2 C38.2 J1.1 L9.1 | length 8.6
  Bottom Layer w0.254: C32.2@1.706,29.401 3.527,29.401 C38.2@3.627,29.501 L9.1@3.627,33.033 ; J1.1@1.709,31.115 L9.1@3.627,33.033 ; L9.1@3.806,33.376 3.806,33.212 L9.1@3.627,33.033
NetR7_2: R7.2 U1.19 | length 1.5
  Top Layer w0.254: R7.2@32.898,22.479 32.904,22.473 32.904,22.035 32.888,22.019 32.888,21.619 32.904,21.603 U1.19@32.904,21.045
NetR10_2: R10.2 U1.9 | length 3.8
  Top Layer w0.254: 35.962,17.935 35.962,17.704 v3(36.216,17.45)
  Bottom Layer w0.254: v3(36.216,17.45) 36.216,16.012 37.039,15.189 37.049,15.189 37.308,14.931 R10.2@37.308,14.697
OUT: C12.1 U1.13 | length 2.9
  Top Layer w0.254: U1.13@36.104,20.707 36.104,21.117 v2(36.444,21.457)
  Bottom Layer w0.381: v2(36.444,21.457) 36.845,21.457 37.651,22.263 C12.1@38.146,22.263
PA_BUS: C13.1 C22.1 C31.1 J3.A4 J3.A9 J3.B4 J3.B9 U1.10 | length 12.9
  Top Layer w0.254: U1.10@35.579,19.007 36.778,19.007 37.078,18.707 v1@36.9,18.529 ; 38.004,7.817 38.004,7.388 37.739,7.123 37.761,7.101 38.015,7.101 C22.1@38.094,7.021 ; 38.104,7.717 39.004,7.717 ; J3.B9@42.304,7.767 42.254,7.717 J3.A4@41.044,7.717 39.004,7.717 ; J3.B4@42.304,10.167 42.254,10.217 J3.A9@41.044,10.217 39.454,10.217 38.953,9.715 38.953,7.768 39.004,7.717
  Bottom Layer w0.254: v1@36.012,7.823 v1@36.038,7.798
  other v1: 36.189,6.831 36.975,6.831 36.189,7.701 36.975,7.701 37.066,17.308 37.054,18.009 37.079,18.745
PA_CC1: C41.1 J3.A5 R6.2 U1.7 | length 18.4
  Top Layer w0.254: U1.7@34.904,17.97 34.904,17.237 v6(34.946,17.196) ; v2(39.847,8.215) 40.005,8.215 ; 40.005,8.215 40.007,8.217 J3.A5@41.044,8.217 41.042,8.215 40.005,8.215
  Signal Layer 2 w0.254: v6(34.946,17.196) 34.946,16.231 40.366,10.811 40.366,8.677 39.903,8.215 v2(39.847,8.215)
  Bottom Layer w0.254: v6(34.946,17.196) 34.946,16.164 35.971,15.139 35.971,14.73 R6.2@36.004,14.697 ; C41.1@39.696,7.567 C41.1@39.518,7.567 39.847,7.896 v2(39.847,8.215)
PA_CC2: C42.1 J3.B5 U1.8 | length 15.7
  Top Layer w0.254: U1.8@35.404,17.97 35.404,17.42 35.53,17.294 v6(35.53,17.283)
  Signal Layer 2 w0.254: v6(35.53,17.283) 35.53,16.561 39.684,12.406 42.98,12.406 43.804,11.583 43.804,10.09 43.481,9.767 J3.B5@43.004,9.767
  Bottom Layer w0.254: J3.B5@43.004,9.767 44.391,9.767 C42.1@44.42,9.738
PA_DM: C39.1 J3.A7 J3.B7 U1.5 | length 16.5
  Top Layer w0.254: U1.5@33.904,18.057 33.904,16.863 33.93,16.838 33.929,16.837 33.954,16.811 v5(33.955,16.713) v5(33.955,16.713) ; v2(39.754,9.217) J3.A7@41.044,9.217
  Signal Layer 2 w0.254: v5@33.926,16.685 33.896,16.715 33.917,16.735 33.938,16.713 v5(33.955,16.713) 33.955,15.531 39.754,9.732 v2(39.754,9.217)
  Bottom Layer w0.254: v2(39.754,9.217) 40.004,9.217 40.654,8.567 41.042,8.567 ; C39.1@41.042,7.567 41.042,8.567 ; J3.B7@42.304,8.567 41.042,8.567
PA_DP: C40.1 J3.A6 J3.B6 U1.4 | length 19.9
  Top Layer w0.254: v5(33.396,16.967) 33.404,16.975 U1.4@33.404,18.057 ; 39.799,8.717 J3.A6@41.044,8.717
  Signal Layer 2 w0.254: v5(33.396,16.967) 33.396,15.393 39.237,9.552 39.237,8.039 39.544,7.732 40.976,7.732 41.244,8 41.244,9.016 41.594,9.367 J3.B6@42.304,9.367 ; 39.31,8.723 39.324,8.709 v2(39.622,8.709)
  Bottom Layer w0.254: C40.1@41.042,9.738 41.413,9.367 J3.B6@42.304,9.367
PB_BUS: C16.1 C23.1 J4.A4 J4.A9 J4.B4 J4.B9 U1.12 | length 15.2
  Top Layer w0.254: U1.12@35.579,20.007 36.417,20.007 36.684,20.275 36.684,20.482 ; 38.111,22.114 38.111,24.431 38.004,24.537 C23.1@38.004,27.217 ; C23.1@38.111,27.11 C23.1@38.004,27.217 ; C16.1@38.311,25.017 J4.A4@41.044,25.017 42.254,25.017 J4.B9@42.304,25.067 ; J4.B4@42.304,27.467 42.254,27.517 J4.A9@41.044,27.517 38.304,27.517 C23.1@38.004,27.217
PB_CC1: C45.1 J4.A5 R5.2 U1.15 | length 12.3
  Top Layer w0.254: U1.15@34.904,21.045 34.904,21.777 v3(35.123,21.997) ; v2(40.004,25.517) J4.A5@41.044,25.517
  Signal Layer 2 w0.254: v3(35.123,21.997) 35.142,21.997 35.548,22.403 38.963,22.403 40.004,23.444 v2(40.004,25.517)
  Bottom Layer w0.254: v3(35.123,21.997) 35.123,22.149 35.438,22.463 R5.2@36.571,22.463 ; v2(40.004,25.517) 40.484,25.517 C45.1@40.838,25.162
PB_CC2: C46.1 J4.B5 U1.14 | length 15.6
  Top Layer w0.254: U1.14@35.404,21.045 35.404,21.559 35.74,21.895 v3(35.758,21.895)
  Signal Layer 2 w0.254: v3(35.758,21.895) 35.803,21.94 41.831,21.94 42.718,22.827 43.484,22.827 44.004,23.347 44.004,26.74 43.677,27.067 J4.B5@43.004,27.067
  Bottom Layer w0.254: J4.B5@43.004,27.067 44.262,27.067 C46.1@44.267,27.061
PB_DM: C43.1 J4.A7 J4.B7 U1.17 | length 15.7
  Top Layer w0.254: v2(33.904,21.819) v2(33.904,21.819) U1.17@33.904,20.957 ; v2(39.982,26.517) J4.A7@41.044,26.517
  Signal Layer 2 w0.254: v2(33.904,21.819) 34.971,22.886 38.425,22.886 39.522,23.982 39.522,26.017 39.982,26.478 v2(39.982,26.517) 41.598,26.517 42.248,25.867 J4.B7@42.304,25.867
  Bottom Layer w0.254: C43.1@40.838,27.061 42.033,25.867 J4.B7@42.304,25.867
PB_DP: C44.1 J4.A6 J4.B6 U1.18 | length 16.3
  Top Layer w0.254: v2(33.371,21.819) 33.396,21.819 33.404,21.811 U1.18@33.404,20.957 ; v2(39.467,26.645) 39.467,26.349 39.8,26.017 J4.A6@41.044,26.017
  Signal Layer 2 w0.254: v2(33.371,21.819) 33.371,21.968 34.746,23.343 37.968,23.343 39.064,24.439 39.064,26.242 v2(39.467,26.645) 39.467,26.684 39.783,27 39.982,26.999 41.777,27 42.111,26.667 J4.B6@42.304,26.667
  Bottom Layer w0.254: C44.1@38.603,27.061 39.019,26.645 v2(39.467,26.645)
